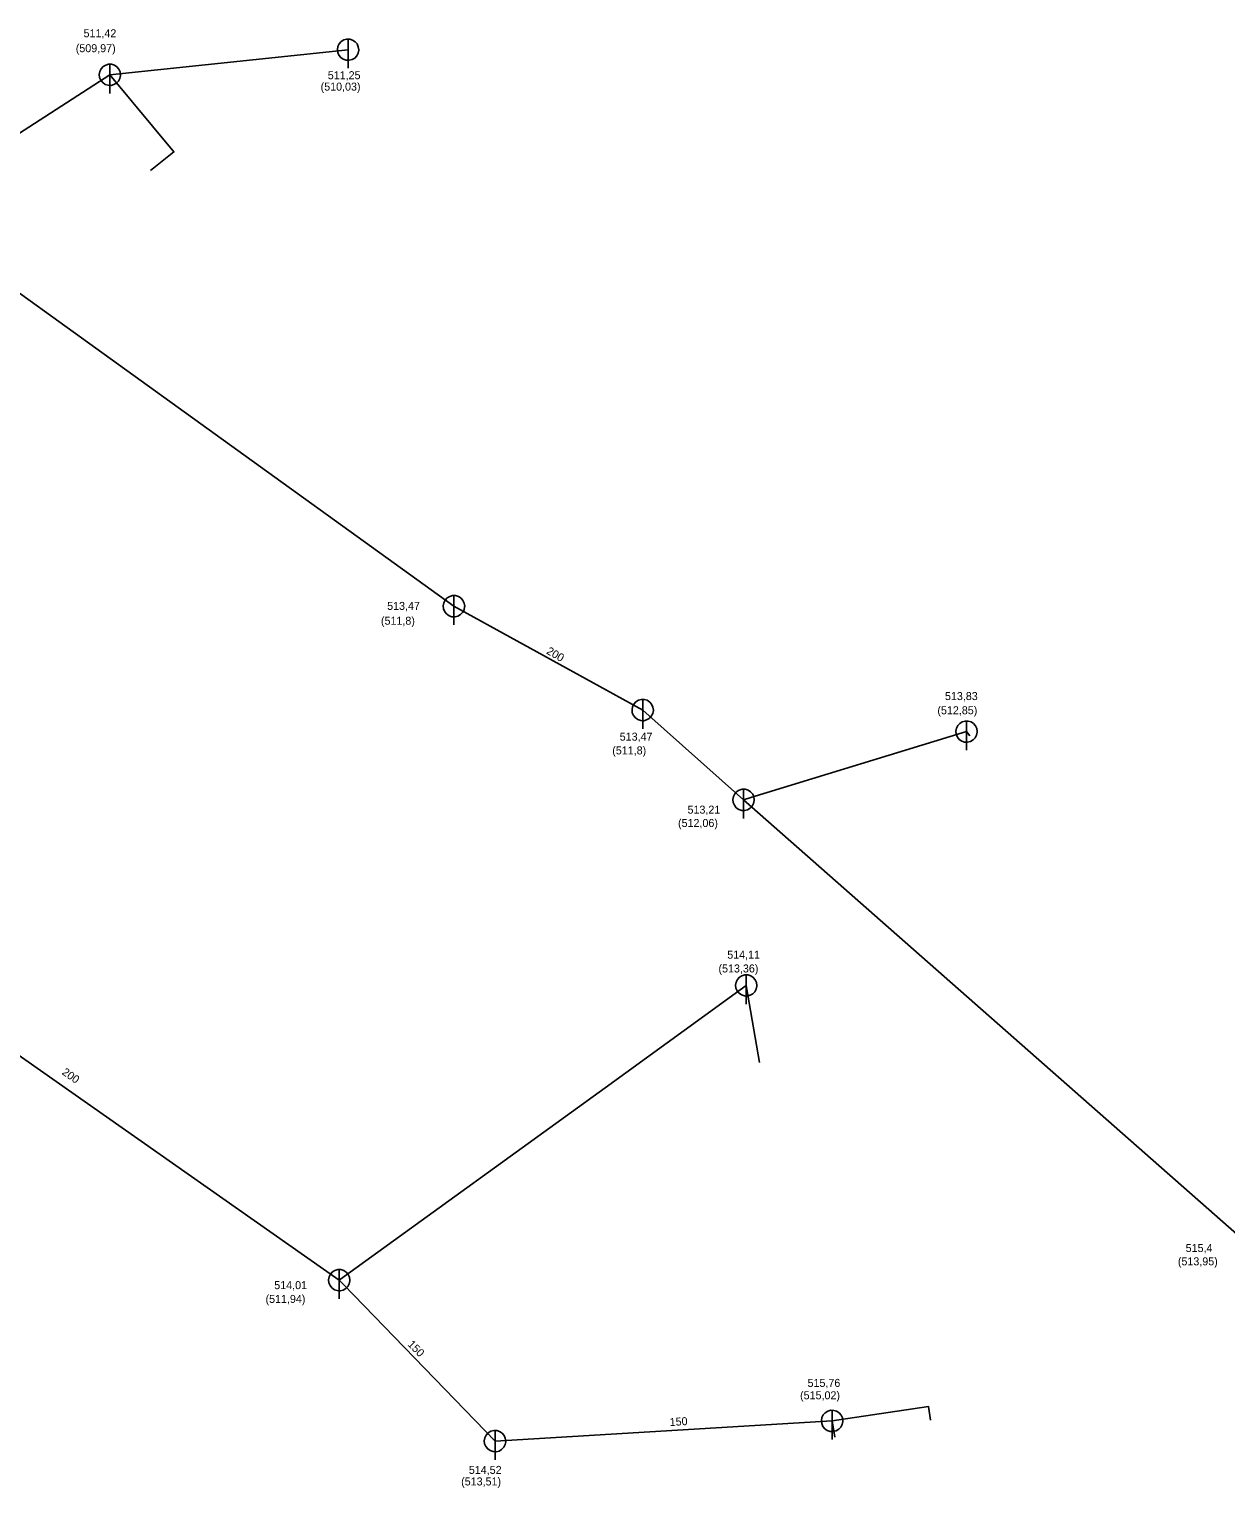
# Model space of a CAD drawing. Extents: x -476058 to -471893, y -1155786 to -1152000.
# Drawn here: x -475058.6 to -474946.6, y -1154413.9 to -1154277.2 of the extents above; entities that cross this region are included whole.
import ezdxf

# ---------------------------------------------------------------- set-up
doc = ezdxf.new("R2010")
doc.units = 0
for name, color, linetype in [('Vrstva 10', 7, 'Continuous'), ('Vrstva 18', 7, 'Continuous'), ('Vrstva 19', 7, 'Continuous'), ('Vrstva 3', 7, 'Continuous'), ('Vrstva 4', 7, 'Continuous'), ('Vrstva 45', 7, 'Continuous'), ('Vrstva 50', 7, 'Continuous'), ('Vrstva 51', 7, 'Continuous')]:
    doc.layers.add(name, color=color, linetype=linetype)

msp = doc.modelspace()

# ---------------------------------------------------------------- linework, layer by layer
at = {"layer": 'Vrstva 10'}
for p, q in [((-475028.76, -1154278.13), (-475028.76, -1154280.87)), ((-475051.06, -1154280.47), (-475051.06, -1154283.22)), ((-475018.84, -1154330.26), (-475018.84, -1154333.01)), ((-475001.17, -1154339.99), (-475001.17, -1154342.74)), ((-474970.84, -1154342.01), (-474970.84, -1154344.76)), ((-474991.72, -1154348.41), (-474991.72, -1154351.16)), ((-474991.47, -1154365.79), (-474991.47, -1154368.54)), ((-475029.59, -1154393.41), (-475029.59, -1154396.16)), ((-474983.43, -1154406.59), (-474983.43, -1154409.34)), ((-475015, -1154408.49), (-475015, -1154411.24))]:
    msp.add_line(p, q, dxfattribs=at)
for points in [[(-475027.76, -1154279.13), (-475027.8, -1154278.85), (-475027.92, -1154278.59), (-475028.1, -1154278.38), (-475028.33, -1154278.22), (-475028.6, -1154278.14), (-475028.89, -1154278.13), (-475029.16, -1154278.21), (-475029.4, -1154278.36), (-475029.59, -1154278.57), (-475029.71, -1154278.82), (-475029.76, -1154279.1), (-475029.73, -1154279.38), (-475029.62, -1154279.64), (-475029.44, -1154279.86), (-475029.21, -1154280.02), (-475028.94, -1154280.11), (-475028.66, -1154280.12), (-475028.39, -1154280.05), (-475028.14, -1154279.91), (-475027.95, -1154279.71), (-475027.82, -1154279.46), (-475027.76, -1154279.18), (-475027.76, -1154279.13)], [(-475050.06, -1154281.47), (-475050.1, -1154281.2), (-475050.22, -1154280.94), (-475050.4, -1154280.72), (-475050.64, -1154280.57), (-475050.91, -1154280.49), (-475051.19, -1154280.48), (-475051.46, -1154280.56), (-475051.7, -1154280.71), (-475051.89, -1154280.91), (-475052.01, -1154281.17), (-475052.06, -1154281.45), (-475052.03, -1154281.73), (-475051.92, -1154281.99), (-475051.74, -1154282.21), (-475051.51, -1154282.37), (-475051.24, -1154282.46), (-475050.96, -1154282.47), (-475050.69, -1154282.4), (-475050.44, -1154282.26), (-475050.25, -1154282.06), (-475050.12, -1154281.81), (-475050.06, -1154281.53), (-475050.06, -1154281.47)], [(-475017.84, -1154331.26), (-475017.88, -1154330.98), (-475018, -1154330.73), (-475018.18, -1154330.51), (-475018.42, -1154330.36), (-475018.69, -1154330.27), (-475018.97, -1154330.27), (-475019.24, -1154330.34), (-475019.48, -1154330.49), (-475019.67, -1154330.7), (-475019.8, -1154330.96), (-475019.84, -1154331.23), (-475019.81, -1154331.52), (-475019.7, -1154331.78), (-475019.53, -1154331.99), (-475019.29, -1154332.16), (-475019.03, -1154332.25), (-475018.74, -1154332.26), (-475018.47, -1154332.19), (-475018.23, -1154332.05), (-475018.03, -1154331.84), (-475017.9, -1154331.59), (-475017.85, -1154331.32), (-475017.84, -1154331.26)], [(-475000.17, -1154340.99), (-475000.21, -1154340.71), (-475000.33, -1154340.45), (-475000.51, -1154340.24), (-475000.74, -1154340.08), (-475001.02, -1154340), (-475001.3, -1154340), (-475001.57, -1154340.07), (-475001.81, -1154340.22), (-475002, -1154340.43), (-475002.12, -1154340.68), (-475002.17, -1154340.96), (-475002.14, -1154341.24), (-475002.03, -1154341.5), (-475001.85, -1154341.72), (-475001.62, -1154341.88), (-475001.35, -1154341.97), (-475001.07, -1154341.99), (-475000.8, -1154341.92), (-475000.55, -1154341.78), (-475000.36, -1154341.57), (-475000.23, -1154341.32), (-475000.17, -1154341.05), (-475000.17, -1154340.99)], [(-474969.84, -1154343.01), (-474969.88, -1154342.73), (-474970, -1154342.47), (-474970.18, -1154342.26), (-474970.42, -1154342.1), (-474970.69, -1154342.02), (-474970.97, -1154342.02), (-474971.24, -1154342.09), (-474971.48, -1154342.24), (-474971.67, -1154342.45), (-474971.79, -1154342.7), (-474971.84, -1154342.98), (-474971.81, -1154343.26), (-474971.7, -1154343.52), (-474971.52, -1154343.74), (-474971.29, -1154343.9), (-474971.03, -1154343.99), (-474970.74, -1154344), (-474970.47, -1154343.94), (-474970.23, -1154343.79), (-474970.03, -1154343.59), (-474969.9, -1154343.34), (-474969.84, -1154343.06), (-474969.84, -1154343.01)], [(-474990.72, -1154349.41), (-474990.76, -1154349.13), (-474990.87, -1154348.87), (-474991.06, -1154348.66), (-474991.29, -1154348.51), (-474991.56, -1154348.42), (-474991.85, -1154348.42), (-474992.12, -1154348.49), (-474992.36, -1154348.64), (-474992.55, -1154348.85), (-474992.67, -1154349.1), (-474992.72, -1154349.38), (-474992.69, -1154349.66), (-474992.58, -1154349.92), (-474992.4, -1154350.14), (-474992.17, -1154350.3), (-474991.9, -1154350.39), (-474991.62, -1154350.41), (-474991.34, -1154350.34), (-474991.1, -1154350.2), (-474990.91, -1154349.99), (-474990.78, -1154349.74), (-474990.72, -1154349.47), (-474990.72, -1154349.41)], [(-474990.47, -1154366.79), (-474990.51, -1154366.52), (-474990.63, -1154366.26), (-474990.81, -1154366.04), (-474991.04, -1154365.89), (-474991.32, -1154365.81), (-474991.6, -1154365.8), (-474991.87, -1154365.88), (-474992.11, -1154366.03), (-474992.3, -1154366.24), (-474992.42, -1154366.49), (-474992.47, -1154366.77), (-474992.44, -1154367.05), (-474992.33, -1154367.31), (-474992.15, -1154367.53), (-474991.92, -1154367.69), (-474991.65, -1154367.78), (-474991.37, -1154367.79), (-474991.1, -1154367.72), (-474990.85, -1154367.58), (-474990.66, -1154367.38), (-474990.53, -1154367.13), (-474990.47, -1154366.85), (-474990.47, -1154366.79)], [(-475028.59, -1154394.41), (-475028.63, -1154394.13), (-475028.75, -1154393.87), (-475028.93, -1154393.66), (-475029.17, -1154393.51), (-475029.43, -1154393.42), (-475029.72, -1154393.42), (-475029.99, -1154393.49), (-475030.23, -1154393.64), (-475030.42, -1154393.85), (-475030.54, -1154394.1), (-475030.59, -1154394.38), (-475030.56, -1154394.66), (-475030.45, -1154394.92), (-475030.27, -1154395.14), (-475030.04, -1154395.3), (-475029.77, -1154395.39), (-475029.49, -1154395.41), (-475029.22, -1154395.34), (-475028.97, -1154395.2), (-475028.78, -1154394.99), (-475028.65, -1154394.74), (-475028.59, -1154394.47), (-475028.59, -1154394.41)], [(-474982.43, -1154407.59), (-474982.47, -1154407.32), (-474982.59, -1154407.06), (-474982.77, -1154406.84), (-474983.01, -1154406.69), (-474983.28, -1154406.61), (-474983.56, -1154406.6), (-474983.83, -1154406.68), (-474984.07, -1154406.83), (-474984.26, -1154407.03), (-474984.38, -1154407.29), (-474984.43, -1154407.57), (-474984.4, -1154407.85), (-474984.29, -1154408.11), (-474984.11, -1154408.33), (-474983.88, -1154408.49), (-474983.61, -1154408.58), (-474983.33, -1154408.59), (-474983.06, -1154408.52), (-474982.81, -1154408.38), (-474982.62, -1154408.18), (-474982.49, -1154407.93), (-474982.43, -1154407.65), (-474982.43, -1154407.59)], [(-475014, -1154409.49), (-475014.04, -1154409.21), (-475014.15, -1154408.95), (-475014.34, -1154408.74), (-475014.57, -1154408.58), (-475014.84, -1154408.5), (-475015.12, -1154408.5), (-475015.4, -1154408.57), (-475015.64, -1154408.72), (-475015.83, -1154408.93), (-475015.95, -1154409.18), (-475016, -1154409.46), (-475015.97, -1154409.74), (-475015.86, -1154410), (-475015.68, -1154410.22), (-475015.45, -1154410.38), (-475015.18, -1154410.47), (-475014.9, -1154410.48), (-475014.62, -1154410.42), (-475014.38, -1154410.27), (-475014.18, -1154410.07), (-475014.05, -1154409.82), (-475014, -1154409.54), (-475014, -1154409.49)]]:
    msp.add_lwpolyline(points, dxfattribs=at)
at = {"layer": 'Vrstva 45'}
for points in [[(-475018.84, -1154331.26), (-475070.51, -1154294.03)], [(-475001.17, -1154340.99), (-475018.84, -1154331.26)], [(-474991.72, -1154349.41), (-475001.17, -1154340.99)], [(-474944.74, -1154390.78), (-474991.72, -1154349.41)], [(-475029.59, -1154394.41), (-475082.64, -1154357.17)]]:
    msp.add_lwpolyline(points, dxfattribs=at)
at = {"layer": 'Vrstva 50'}
for p, q in [((-475051.06, -1154281.47), (-475028.76, -1154279.13)), ((-475069.56, -1154293.42), (-475051.06, -1154281.47))]:
    msp.add_line(p, q, dxfattribs=at)
for points in [[(-474970.84, -1154343.01), (-474991.03, -1154349.2)], [(-474991.03, -1154349.2), (-474991.72, -1154349.41)], [(-475004.69, -1154376.38), (-474991.47, -1154366.79)], [(-475029.13, -1154394.07), (-475004.69, -1154376.38)], [(-475029.13, -1154394.07), (-475029.59, -1154394.41)], [(-475029.17, -1154394.84), (-475029.59, -1154394.41)], [(-475029.17, -1154394.84), (-475015, -1154409.49)], [(-474983.43, -1154407.59), (-474974.41, -1154406.24), (-474974.22, -1154407.53)], [(-475015, -1154409.49), (-474983.43, -1154407.59)]]:
    msp.add_lwpolyline(points, dxfattribs=at)
at = {"layer": 'Vrstva 51'}
for p, q in [((-474970.53, -1154343.41), (-474970.84, -1154343.01)), ((-474990.23, -1154374.01), (-474991.47, -1154366.79)), ((-474983.16, -1154409.13), (-474983.43, -1154407.59))]:
    msp.add_line(p, q, dxfattribs=at)
msp.add_lwpolyline([(-475047.27, -1154290.43), (-475045.07, -1154288.7), (-475051.06, -1154281.47)], dxfattribs=at)

# ---------------------------------------------------------------- texts
at = {"layer": 'Vrstva 18'}
for rotation, p in [(329.8894, (-475010.25, -1154335.67)), (324.9319, (-475055.62, -1154375.07))]:
    msp.add_text('200 ', height=0.75, rotation=rotation, dxfattribs=at).set_placement(p)
at = {"layer": 'Vrstva 19'}
for rotation, p in [(314.7263, (-475023.24, -1154400.48)), (3.43, (-474998.62, -1154408.08))]:
    msp.add_text('150 ', height=0.75, rotation=rotation, dxfattribs=at).set_placement(p)
at = {"layer": 'Vrstva 3'}
for s, p in [('511,42', (-475053.53, -1154277.96)), ('511,25', (-475030.66, -1154281.89)), ('513,47', (-475025.1, -1154331.61)), ('513,83', (-474972.86, -1154340.06)), ('513,47', (-475003.32, -1154343.86)), ('513,21', (-474996.97, -1154350.7)), ('514,11', (-474993.25, -1154364.29)), ('515,4', (-474950.32, -1154391.77)), ('514,01', (-475035.67, -1154395.25)), ('515,76', (-474985.73, -1154404.41)), ('514,52', (-475017.45, -1154412.56))]:
    msp.add_text(s, height=0.75, dxfattribs=at).set_placement(p)
at = {"layer": 'Vrstva 4'}
for s, p in [('(509,97)', (-475054.26, -1154279.36)), ('(510,03)', (-475031.33, -1154282.96)), ('(511,8)', (-475025.68, -1154333)), ('(512,85)', (-474973.57, -1154341.39)), ('(511,8)', (-475004.02, -1154345.15)), ('(512,06)', (-474997.86, -1154351.95)), ('(513,36)', (-474994.07, -1154365.58)), ('(513,95)', (-474951.05, -1154393.02)), ('(511,94)', (-475036.49, -1154396.54)), ('(515,02)', (-474986.43, -1154405.57)), ('(513,51)', (-475018.17, -1154413.64))]:
    msp.add_text(s, height=0.75, dxfattribs=at).set_placement(p)

doc.saveas('drawing.dxf')
